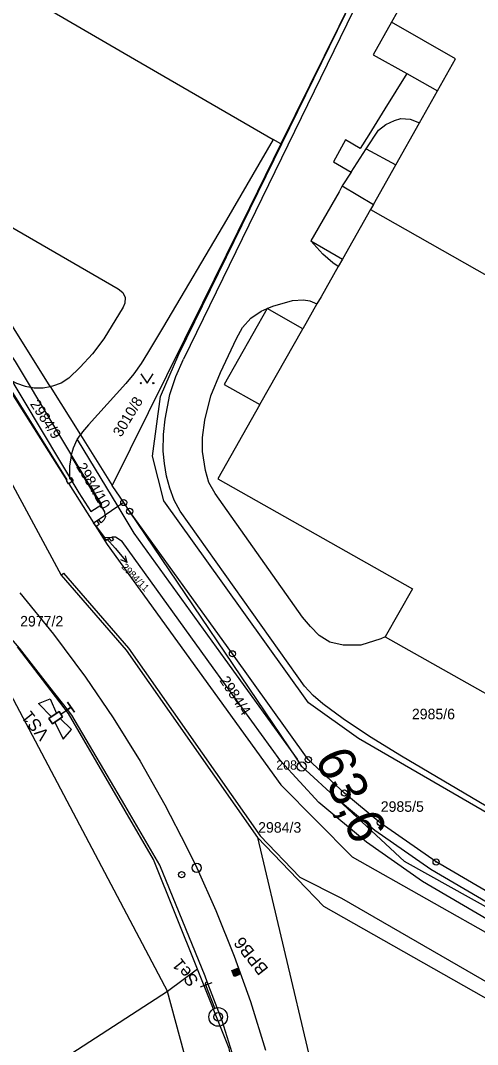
# Model space of a CAD drawing. Extents: x -620475 to -619963, y -1123010 to -1122510.
# Drawn here: x -620181.4 to -620107.7, y -1122849.6 to -1122684.3 of the extents above; entities that cross this region are included whole.
import ezdxf

# ---------------------------------------------------------------- set-up
doc = ezdxf.new("R2010")
doc.units = 0
for name, color, linetype in [('HranDP', 7, 'Continuous'), ('Hranice parcel', 7, 'Continuous'), ('Parcelní čísla', 7, 'Continuous'), ('Pop  PČ popisy', 7, 'Continuous'), ('Vnitřní kresba', 7, 'Continuous'), ('Vrstva 1', 7, 'Continuous'), ('Vrstva 2', 7, 'Continuous'), ('Vrstva 3', 7, 'Continuous'), ('Vrstva 7', 7, 'Continuous'), ('Věcná břemena k části', 7, 'Continuous'), ('Značky bodu BP', 7, 'Continuous'), ('Značky kultur', 7, 'Continuous')]:
    doc.layers.add(name, color=color, linetype=linetype)

msp = doc.modelspace()

# ---------------------------------------------------------------- linework, layer by layer
at = {"layer": 'HranDP'}
for points in [[(-620197.33, -1122735.44), (-620187.9, -1122749.66), (-620174.83, -1122773.82), (-620164.34, -1122785.91), (-620143.18, -1122816.17)], [(-620152.84, -1122837.4), (-620159.98, -1122819.68), (-620173.68, -1122796.12), (-620181.92, -1122785.4)], [(-620143.18, -1122816.17), (-620134.66, -1122852.11), (-620129.18, -1122882.66), (-620128.4, -1122892.9)], [(-620140.38, -1122898.92), (-620140.56, -1122886.8), (-620147.76, -1122850.22), (-620152.84, -1122837.4)]]:
    msp.add_lwpolyline(points, dxfattribs=at)
at = {"layer": 'Hranice parcel'}
for p, q in [((-620144.37, -1122714.62), (-620122.31, -1122669.51)), ((-620127.6, -1122680.22), (-620139.41, -1122704.19)), ((-620139.41, -1122704.19), (-620140.63, -1122703.48)), ((-620176.62, -1122743.36), (-620186.47, -1122727.64)), ((-620152.03, -1122729.88), (-620166.6, -1122759.34)), ((-620176.62, -1122743.36), (-620171.74, -1122751.13)), ((-620171.74, -1122751.13), (-620166.6, -1122759.34)), ((-620164.75, -1122762.08), (-620166.6, -1122759.34)), ((-620163.81, -1122763.48), (-620164.75, -1122762.08))]:
    msp.add_line(p, q, dxfattribs=at)
for points in [[(-620262.42, -1122632.85), (-620187.21, -1122676.39), (-620163.01, -1122690.49), (-620140.63, -1122703.48)], [(-620104.23, -1122665.87), (-620109.38, -1122663), (-620116.98, -1122676.43), (-620121.57, -1122684.55), (-620124.5, -1122689.8), (-620119.11, -1122692.84), (-620122.64, -1122698.55), (-620125.21, -1122702.71), (-620126.59, -1122704.94), (-620128.96, -1122703.55), (-620130.94, -1122707.08), (-620128.08, -1122708.75), (-620129.52, -1122710.96)], [(-620140.63, -1122703.48), (-620148.19, -1122716.42), (-620158.35, -1122733.67), (-620160.91, -1122737.97), (-620161.97, -1122739.66), (-620163.14, -1122741.3), (-620164.41, -1122742.85), (-620170.46, -1122749.51), (-620171.42, -1122750.65), (-620171.74, -1122751.13)], [(-620139.41, -1122704.19), (-620144.48, -1122714.48), (-620152.03, -1122729.88)], [(-620129.52, -1122710.96), (-620130.02, -1122711.91), (-620134.59, -1122719.84), (-620129.48, -1122722.79), (-620130.16, -1122724), (-620132.92, -1122728.86), (-620133.58, -1122730.02), (-620135.85, -1122734.02), (-620141.6, -1122730.74), (-620148.58, -1122743.04), (-620142.8, -1122746.27), (-620149.58, -1122758.23), (-620118.17, -1122776.02), (-620122.58, -1122783.75), (-620090.7, -1122801.75)], [(-620129.52, -1122710.96), (-620124.48, -1122713.98), (-620124.94, -1122714.79), (-620058.31, -1122752.59), (-620054.51, -1122754.74), (-620054.56, -1122754.84)], [(-620191.6, -1122712.59), (-620176.88, -1122721.09), (-620165.63, -1122727.6), (-620164.91, -1122728.17), (-620164.53, -1122728.99), (-620164.6, -1122729.87), (-620164.86, -1122730.54), (-620167.98, -1122735.66), (-620169.77, -1122738.05), (-620171.8, -1122740.25), (-620173.6, -1122742), (-620174.86, -1122742.79), (-620176.26, -1122743.3), (-620176.62, -1122743.36)], [(-620027.34, -1122787.19), (-620029.12, -1122790.47), (-620030.63, -1122793.23), (-620030.93, -1122793.08), (-620062.93, -1122815.9), (-620079.47, -1122827.69), (-620107.97, -1122811.15), (-620126.88, -1122800.18), (-620134.93, -1122794.41), (-620148.77, -1122775.1), (-620158.3, -1122761.8), (-620160.13, -1122754.62), (-620158.82, -1122744.94), (-620155.87, -1122738.11), (-620144.37, -1122714.62)], [(-620197.33, -1122735.44), (-620187.9, -1122749.66), (-620174.83, -1122773.82), (-620164.34, -1122785.91), (-620143.18, -1122816.17)], [(-620173.24, -1122754.52), (-620173.48, -1122756.2), (-620173.53, -1122758.23), (-620173.22, -1122758.03), (-620172.91, -1122758.59), (-620173.61, -1122759.06), (-620173.64, -1122759.08), (-620174, -1122758.53), (-620173.96, -1122758.5), (-620173.87, -1122758.44), (-620183.92, -1122742.28), (-620184.05, -1122742.35), (-620184.39, -1122741.79), (-620183.63, -1122741.31), (-620183.27, -1122741.89), (-620183.57, -1122742.07), (-620182.08, -1122742.82), (-620180.68, -1122743.31), (-620179.21, -1122743.55), (-620177.73, -1122743.55), (-620176.62, -1122743.36)], [(-620173.24, -1122754.52), (-620172.87, -1122753.23), (-620172.25, -1122751.89), (-620171.74, -1122751.13)], [(-620167.73, -1122764.1), (-620167.81, -1122763.6), (-620173.24, -1122754.52)], [(-620164.75, -1122762.08), (-620165.7, -1122762.73), (-620167.73, -1122764.1)], [(-620169.18, -1122765.95), (-620169.61, -1122765.37), (-620167.73, -1122764.1)], [(-620072.47, -1122846.25), (-620119.48, -1122820.03), (-620130.17, -1122810.08), (-620136, -1122804.68), (-620136.79, -1122803.52), (-620163.81, -1122763.48)], [(-620069.79, -1122845.77), (-620093.24, -1122832.45), (-620114.36, -1122820.1), (-620123.37, -1122813.77), (-620129.15, -1122808.98), (-620134.98, -1122803.58), (-620147.22, -1122786.5), (-620163.81, -1122763.48)], [(-620169.18, -1122765.95), (-620167.86, -1122767.72), (-620166.7, -1122767.69)], [(-620166.7, -1122767.69), (-620166.41, -1122768.09), (-620166.72, -1122768.33), (-620167.06, -1122767.87), (-620167.55, -1122768.23), (-620169.18, -1122765.95)], [(-620074.02, -1122848.16), (-620095.17, -1122835.78), (-620116.57, -1122823.25), (-620125.58, -1122816.92), (-620133.3, -1122810.53), (-620139.43, -1122803.84), (-620150.35, -1122788.75), (-620165.02, -1122768.39), (-620166.09, -1122767.67), (-620166.7, -1122767.69)], [(-620152.84, -1122837.4), (-620159.98, -1122819.68), (-620173.68, -1122796.12), (-620181.92, -1122785.4)], [(-620143.18, -1122816.17), (-620134.66, -1122852.11), (-620129.18, -1122882.66), (-620128.4, -1122892.9)], [(-620080.86, -1122856.55), (-620132.47, -1122827.27), (-620136.72, -1122822.9), (-620143.18, -1122816.17)], [(-620152.84, -1122837.4), (-620157.72, -1122840.99), (-620239.08, -1122893.74)], [(-620140.38, -1122898.92), (-620140.56, -1122886.8), (-620147.76, -1122850.22), (-620152.84, -1122837.4)]]:
    msp.add_lwpolyline(points, dxfattribs=at)
at = {"layer": 'Pop  PČ popisy'}
for p, q in [((-620167.46, -1122767.92), (-620166.15, -1122769.46)), ((-620166.15, -1122769.46), (-620164.22, -1122771.76)), ((-620164.22, -1122771.76), (-620165.25, -1122771.31)), ((-620164.22, -1122771.76), (-620164.48, -1122770.67))]:
    msp.add_line(p, q, dxfattribs=at)
at = {"layer": 'Vnitřní kresba'}
for p, q in [((-620113.99, -1122654.48), (-620155.13, -1122738.93)), ((-620111.24, -1122690.45), (-620121.57, -1122684.55)), ((-620114.16, -1122695.63), (-620111.24, -1122690.45)), ((-620119.11, -1122692.84), (-620114.16, -1122695.63)), ((-620117.05, -1122700.78), (-620114.16, -1122695.63)), ((-620122.46, -1122701.03), (-620121.09, -1122700.41)), ((-620121.09, -1122700.41), (-620120.08, -1122700.09)), ((-620120.08, -1122700.09), (-620118.57, -1122700.21)), ((-620118.57, -1122700.21), (-620117.05, -1122700.78)), ((-620125.62, -1122704.98), (-620123.65, -1122701.96)), ((-620123.65, -1122701.96), (-620122.46, -1122701.03)), ((-620120.87, -1122707.56), (-620117.05, -1122700.78)), ((-620128.08, -1122708.75), (-620125.62, -1122704.98)), ((-620125.62, -1122704.98), (-620120.87, -1122707.56)), ((-620124.48, -1122713.98), (-620120.87, -1122707.56)), ((-620124.94, -1122714.79), (-620129.48, -1122722.79)), ((-620132.63, -1122721.98), (-620134.59, -1122719.84)), ((-620131.03, -1122723.38), (-620132.63, -1122721.98)), ((-620130.16, -1122724), (-620131.03, -1122723.38)), ((-620140.72, -1122730.36), (-620137.55, -1122729.49)), ((-620137.55, -1122729.49), (-620135.75, -1122729.37)), ((-620135.75, -1122729.37), (-620134.75, -1122729.52)), ((-620134.75, -1122729.52), (-620133.58, -1122730.02)), ((-620191.31, -1122731.11), (-620173.96, -1122758.5)), ((-620144.26, -1122732.31), (-620142.59, -1122731.16)), ((-620142.59, -1122731.16), (-620141.6, -1122730.74)), ((-620141.6, -1122730.74), (-620140.72, -1122730.36)), ((-620145.58, -1122733.83), (-620144.26, -1122732.31)), ((-620146.56, -1122735.6), (-620145.58, -1122733.83)), ((-620142.8, -1122746.27), (-620135.85, -1122734.02)), ((-620149.15, -1122741.1), (-620146.56, -1122735.6)), ((-620156.36, -1122741.72), (-620155.13, -1122738.93)), ((-620157.32, -1122744.66), (-620156.36, -1122741.72)), ((-620150.71, -1122744.84), (-620149.15, -1122741.1)), ((-620158.07, -1122748.62), (-620157.32, -1122744.66)), ((-620151.67, -1122748.77), (-620150.71, -1122744.84)), ((-620158.33, -1122751.09), (-620158.07, -1122748.62)), ((-620152.03, -1122751.56), (-620151.67, -1122748.77)), ((-620158.37, -1122753.78), (-620158.33, -1122751.09)), ((-620152.03, -1122753.86), (-620152.03, -1122751.56)), ((-620172.25, -1122751.89), (-620165.7, -1122762.73)), ((-620158.2, -1122755.8), (-620158.37, -1122753.78)), ((-620151.58, -1122756.91), (-620152.03, -1122753.86)), ((-620157.86, -1122757.82), (-620158.2, -1122755.8)), ((-620157.34, -1122759.76), (-620157.86, -1122757.82)), ((-620151.04, -1122758.86), (-620151.58, -1122756.91)), ((-620173.61, -1122759.06), (-620169.61, -1122765.37)), ((-620156.64, -1122761.69), (-620157.34, -1122759.76)), ((-620150.03, -1122760.6), (-620151.04, -1122758.86)), ((-620135.93, -1122780.56), (-620150.03, -1122760.6)), ((-620165.7, -1122762.73), (-620163.11, -1122767.02)), ((-620155.67, -1122763.48), (-620156.64, -1122761.69)), ((-620168.75, -1122764.87), (-620169.05, -1122765.1)), ((-620168.38, -1122765.37), (-620168.75, -1122764.87)), ((-620167.68, -1122764.39), (-620167.95, -1122764.93)), ((-620167.73, -1122764.1), (-620167.68, -1122764.39)), ((-620136.78, -1122790.07), (-620155.67, -1122763.48)), ((-620169.61, -1122765.37), (-620167.41, -1122768.84)), ((-620168.7, -1122765.62), (-620169.18, -1122765.95)), ((-620169.05, -1122765.1), (-620168.7, -1122765.62)), ((-620167.95, -1122764.93), (-620168.38, -1122765.37)), ((-620163.11, -1122767.02), (-620148.44, -1122787.38)), ((-620167.41, -1122768.84), (-620139.39, -1122807.63)), ((-620174.83, -1122773.82), (-620174.45, -1122773.49)), ((-620174.45, -1122773.49), (-620163.96, -1122785.58)), ((-620134.64, -1122782.1), (-620135.93, -1122780.56)), ((-620133.21, -1122783.55), (-620134.64, -1122782.1)), ((-620131.49, -1122784.61), (-620133.21, -1122783.55)), ((-620163.96, -1122785.58), (-620142.77, -1122815.89)), ((-620185.65, -1122788.07), (-620157.72, -1122840.99)), ((-620148.44, -1122787.38), (-620136.79, -1122803.52)), ((-620135.58, -1122791.72), (-620136.78, -1122790.07)), ((-620134.2, -1122793.25), (-620135.58, -1122791.72)), ((-620132.61, -1122794.57), (-620134.2, -1122793.25)), ((-620129.33, -1122796.98), (-620132.61, -1122794.57)), ((-620125.13, -1122799.85), (-620129.33, -1122796.98)), ((-620119.93, -1122803.03), (-620125.13, -1122799.85)), ((-620104.17, -1122812.35), (-620119.93, -1122803.03)), ((-620139.39, -1122807.63), (-620127.92, -1122819.29)), ((-620124.23, -1122815), (-620130.17, -1122810.08)), ((-620142.77, -1122815.89), (-620136.36, -1122822.55)), ((-620115.22, -1122821.33), (-620124.23, -1122815)), ((-620127.92, -1122819.29), (-620075.39, -1122849.03)), ((-620136.36, -1122822.55), (-620129.64, -1122825.94)), ((-620093.98, -1122833.75), (-620115.22, -1122821.33)), ((-620129.64, -1122825.94), (-620104.21, -1122840.64)), ((-620149.02, -1122872.99), (-620157.72, -1122840.99))]:
    msp.add_line(p, q, dxfattribs=at)
msp.add_lwpolyline([(-620122.58, -1122783.75), (-620123.27, -1122784.1), (-620126.53, -1122785.08), (-620129.37, -1122785.1), (-620131.49, -1122784.61)], dxfattribs=at)
at = {"layer": 'Vrstva 1'}
msp.add_line((-620173.25, -1122795.11), (-620173.84, -1122795.49), dxfattribs=at)
for points in [[(-620173.84, -1122795.49), (-620176.67, -1122791.87), (-620181.59, -1122785.57), (-620185.43, -1122781.13), (-620190.33, -1122775.52), (-620190.05, -1122772.28), (-620198.93, -1122763.63), (-620211.63, -1122752.65), (-620228.5, -1122738.51), (-620248.32, -1122722.77)], [(-620181.54, -1122776.64), (-620176.09, -1122783.33), (-620170.93, -1122790.27), (-620166.46, -1122796.85), (-620162.11, -1122803.84), (-620158.13, -1122810.88), (-620154.63, -1122817.64), (-620152.99, -1122821.05), (-620149.89, -1122827.96), (-620146.96, -1122835.3), (-620144.33, -1122842.64), (-620141.9, -1122850.48)], [(-620151.28, -1122839.45), (-620151.64, -1122838.53), (-620158.91, -1122820.61), (-620164.59, -1122810.94), (-620173.13, -1122796.4), (-620173.84, -1122795.49)], [(-620151.28, -1122839.45), (-620151.63, -1122839.59), (-620151.49, -1122839.98)], [(-620140.39, -1122873.11), (-620142.65, -1122873.56), (-620146.97, -1122851.79), (-620148.85, -1122845.74), (-620151.28, -1122839.45)]]:
    msp.add_lwpolyline(points, dxfattribs=at)
at = {"layer": 'Vrstva 2'}
for p, q in [((-620173.82, -1122794.29), (-620172.68, -1122795.93)), ((-620172.68, -1122795.93), (-620173.82, -1122794.29)), ((-620174.9, -1122796.25), (-620173.25, -1122795.11)), ((-620174.9, -1122796.25), (-620173.25, -1122795.11)), ((-620147.26, -1122837.61), (-620145.98, -1122838.16)), ((-620147.09, -1122837.54), (-620146.05, -1122837.99)), ((-620146.92, -1122837.47), (-620146.12, -1122837.82)), ((-620146.75, -1122837.4), (-620146.19, -1122837.64)), ((-620146.58, -1122837.33), (-620146.26, -1122837.47)), ((-620146.4, -1122837.27), (-620146.33, -1122837.3)), ((-620147.28, -1122837.75), (-620146.07, -1122838.27)), ((-620147.21, -1122837.92), (-620146.25, -1122838.33)), ((-620147.14, -1122838.09), (-620146.42, -1122838.4)), ((-620147.07, -1122838.26), (-620146.59, -1122838.47)), ((-620147, -1122838.44), (-620146.76, -1122838.54)), ((-620150.55, -1122839.62), (-620152.42, -1122840.34)), ((-620150.06, -1122843.72), (-620151.49, -1122839.98))]:
    msp.add_line(p, q, dxfattribs=at)
for points in [[(-620176.42, -1122796.69), (-620178.53, -1122794.5), (-620176.6, -1122793.78), (-620175.59, -1122796.12)], [(-620176.83, -1122796.97), (-620176.26, -1122797.8), (-620174.61, -1122796.66), (-620175.18, -1122795.84)], [(-620176.26, -1122797.8), (-620176.83, -1122796.97), (-620175.18, -1122795.84), (-620174.61, -1122796.66)], [(-620175.85, -1122797.51), (-620174.55, -1122800.26), (-620173.19, -1122798.72), (-620175.03, -1122796.94)], [(-620146.35, -1122837.24), (-620145.96, -1122838.22), (-620146.93, -1122838.61), (-620147.32, -1122837.63)], [(-620146.35, -1122837.24), (-620145.96, -1122838.22), (-620146.93, -1122838.61), (-620147.32, -1122837.63)]]:
    msp.add_lwpolyline(points, close=True, dxfattribs=at)
for radius in [1.5, 0.7]:
    msp.add_circle((-620149.52, -1122845.12), radius, dxfattribs=at)
at = {"layer": 'Vrstva 7'}
msp.add_line((-620155.44, -1122822.09), (-620155.4, -1122822.18), dxfattribs=at)
for centre, radius in [((-620152.99, -1122821.05), 0.75), ((-620155.42, -1122822.14), 0.5)]:
    msp.add_circle(centre, radius, dxfattribs=at)
at = {"layer": 'Věcná břemena k části'}
msp.add_lwpolyline([(-620187.14, -1122731.99), (-620188.79, -1122733.18), (-620187.68, -1122734.99), (-620184.01, -1122740.44), (-620172.01, -1122760.53), (-620170.08, -1122763.54), (-620168.3, -1122762.4), (-620170.19, -1122759.45), (-620182.21, -1122739.32)], close=True, dxfattribs=at)
at = {"layer": 'Značky bodu BP'}
for centre, radius in [((-620164.75, -1122762.08), 0.5), ((-620164.75, -1122762.08), 0.0303), ((-620163.81, -1122763.48), 0.5), ((-620163.81, -1122763.48), 0.0303), ((-620147.22, -1122786.5), 0.5), ((-620147.22, -1122786.5), 0.0303), ((-620136.05, -1122804.7), 0.75), ((-620134.98, -1122803.58), 0.5), ((-620134.98, -1122803.58), 0.0303), ((-620136.05, -1122804.7), 0.03), ((-620129.15, -1122808.98), 0.5), ((-620129.15, -1122808.98), 0.0303), ((-620123.37, -1122813.77), 0.5), ((-620123.37, -1122813.77), 0.0303), ((-620114.36, -1122820.1), 0.5), ((-620114.36, -1122820.1), 0.0303)]:
    msp.add_circle(centre, radius, dxfattribs=at)
at = {"layer": 'Značky kultur'}
msp.add_lwpolyline([(-620161.99, -1122741.3), (-620160.99, -1122742.8), (-620159.99, -1122741.3)], dxfattribs=at)
for centre in [(-620161.99, -1122742.8), (-620159.99, -1122742.8)]:
    msp.add_circle(centre, 0.1, dxfattribs=at)

# ---------------------------------------------------------------- texts
at = {"layer": 'Parcelní čísla'}
for s, height, rotation, p in [('3010/8', 1.7, 59, (-620165.17, -1122751.62)), ('2984/9', 1.7, 303, (-620179.93, -1122746.16)), ('2984/10', 1.7, 301, (-620172.47, -1122756.29)), ('2984/11', 1.139, 314, (-620165.2, -1122772.57)), ('2984/4', 1.7, 303, (-620149.36, -1122790.78))]:
    msp.add_text(s, height=height, rotation=rotation, dxfattribs=at).set_placement(p)
for s, p in [('2977/2', (-620181.47, -1122782.09)), ('2985/6', (-620118.27, -1122797.07)), ('2985/5', (-620123.29, -1122812.01)), ('2984/3', (-620143.07, -1122815.38))]:
    msp.add_text(s, height=1.7, dxfattribs=at).set_placement(p)
at = {"layer": 'Vrstva 3'}
for s, p in [('VS1', (-620176.65, -1122799.48)), ('BPB6', (-620141.32, -1122837.34)), ('Se1', (-620152.57, -1122839.22))]:
    msp.add_text(s, height=2, rotation=128.542, dxfattribs=at).set_placement(p)
at = {"layer": 'Vrstva 7'}
msp.add_text('63,6', height=6, rotation=294.1767, dxfattribs=at).set_placement((-620133.97, -1122803.32))
at = {"layer": 'Značky bodu BP'}
msp.add_text('208', height=1.5, dxfattribs=at).set_placement((-620140.15, -1122805.2))

doc.saveas('drawing.dxf')
